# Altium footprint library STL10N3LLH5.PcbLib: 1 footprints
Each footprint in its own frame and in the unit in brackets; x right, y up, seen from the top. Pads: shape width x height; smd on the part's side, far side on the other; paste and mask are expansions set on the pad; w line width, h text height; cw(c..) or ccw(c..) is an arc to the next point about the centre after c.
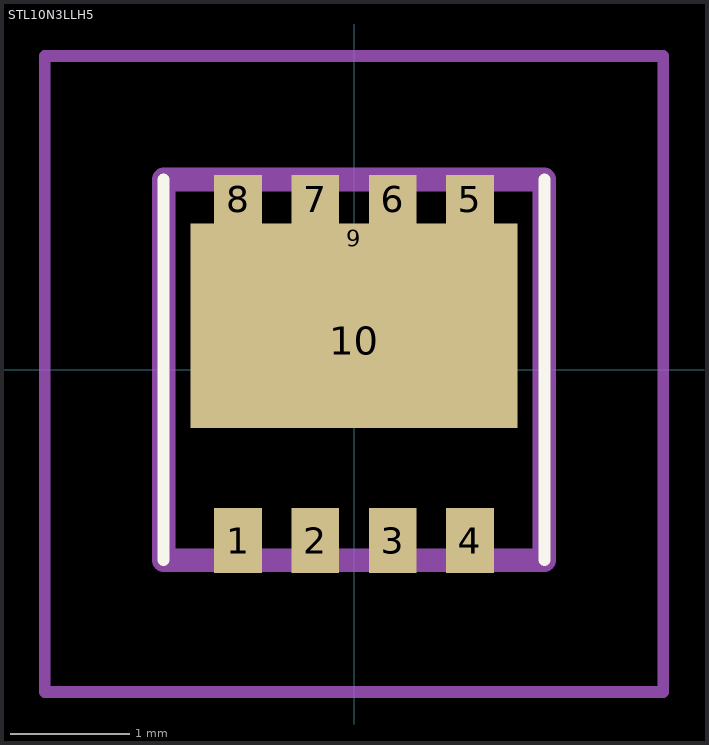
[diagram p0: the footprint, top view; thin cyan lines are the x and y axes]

## STL10N3LLH5 [mm]
pads (10):
  rect 0.4x0.55 smd: 1(-0.975,-1.435) 2(-0.325,-1.435) 3(0.325,-1.435) 4(0.975,-1.435)
  rect 0.4x0.41 smd: 5(0.975,1.435) 6(0.325,1.435) 7(-0.325,1.435) 8(-0.975,1.435)
  rect 2.75x0.25 smd: 9(0,1.105)
  rect 2.75x1.47 smd: 10(0,0.245)
Top Overlay:
  lines w0.1: -1.6,-1.6 -1.6,1.6 ; 1.6,-1.6 1.6,1.6
Mechanical 15:
  lines w0.2: -1.6,-1.6 1.6,-1.6 1.6,1.6 -1.6,1.6 -1.6,-1.6
Mechanical 20:
  lines w0.1: -2.6,-2.71 2.6,-2.71 2.6,2.64 -2.6,2.64 -2.6,-2.71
